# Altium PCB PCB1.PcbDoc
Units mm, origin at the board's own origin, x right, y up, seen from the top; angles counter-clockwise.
Board outline 23.88 x 30.86 mm, 2 copper layers (Top Layer, Bottom Layer); 7 components, 4 nets, 15 pads, 0 vias.
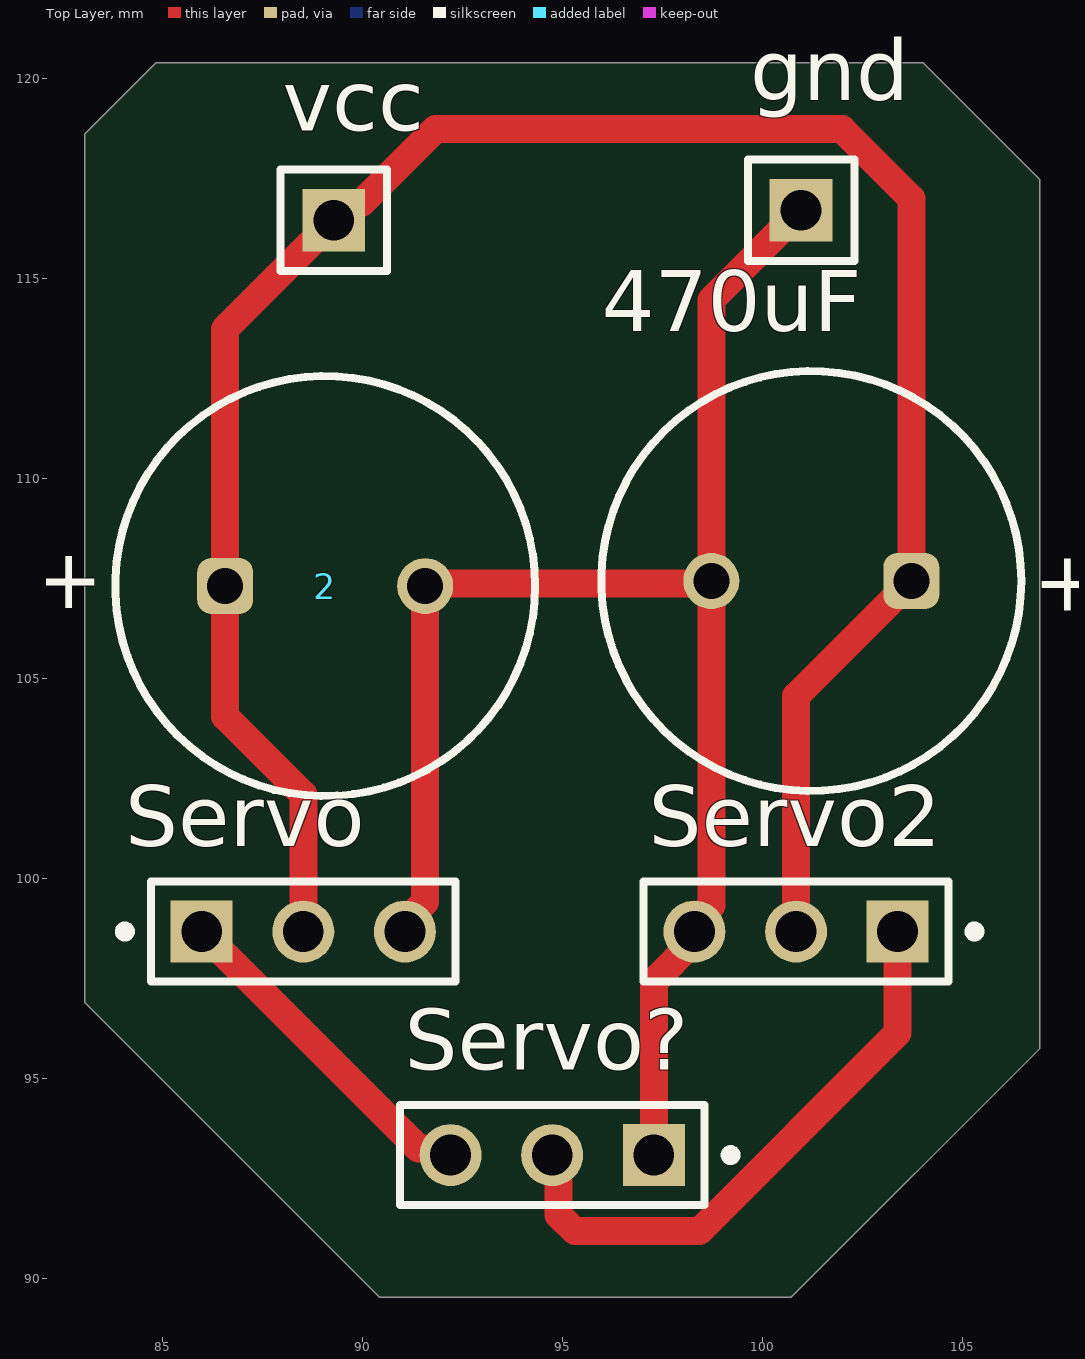
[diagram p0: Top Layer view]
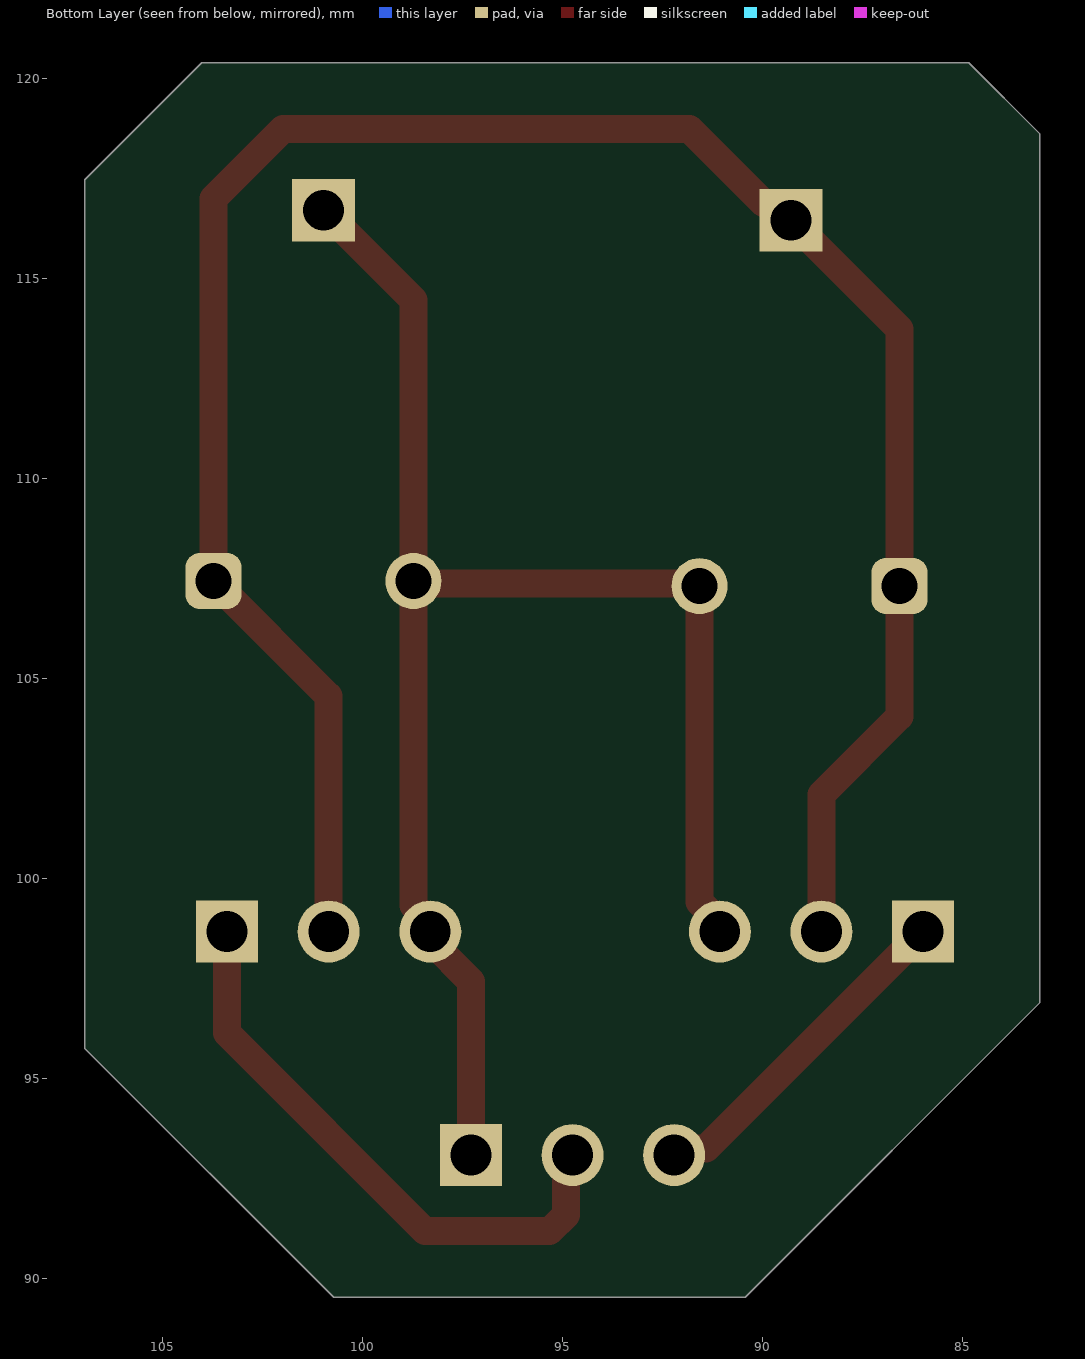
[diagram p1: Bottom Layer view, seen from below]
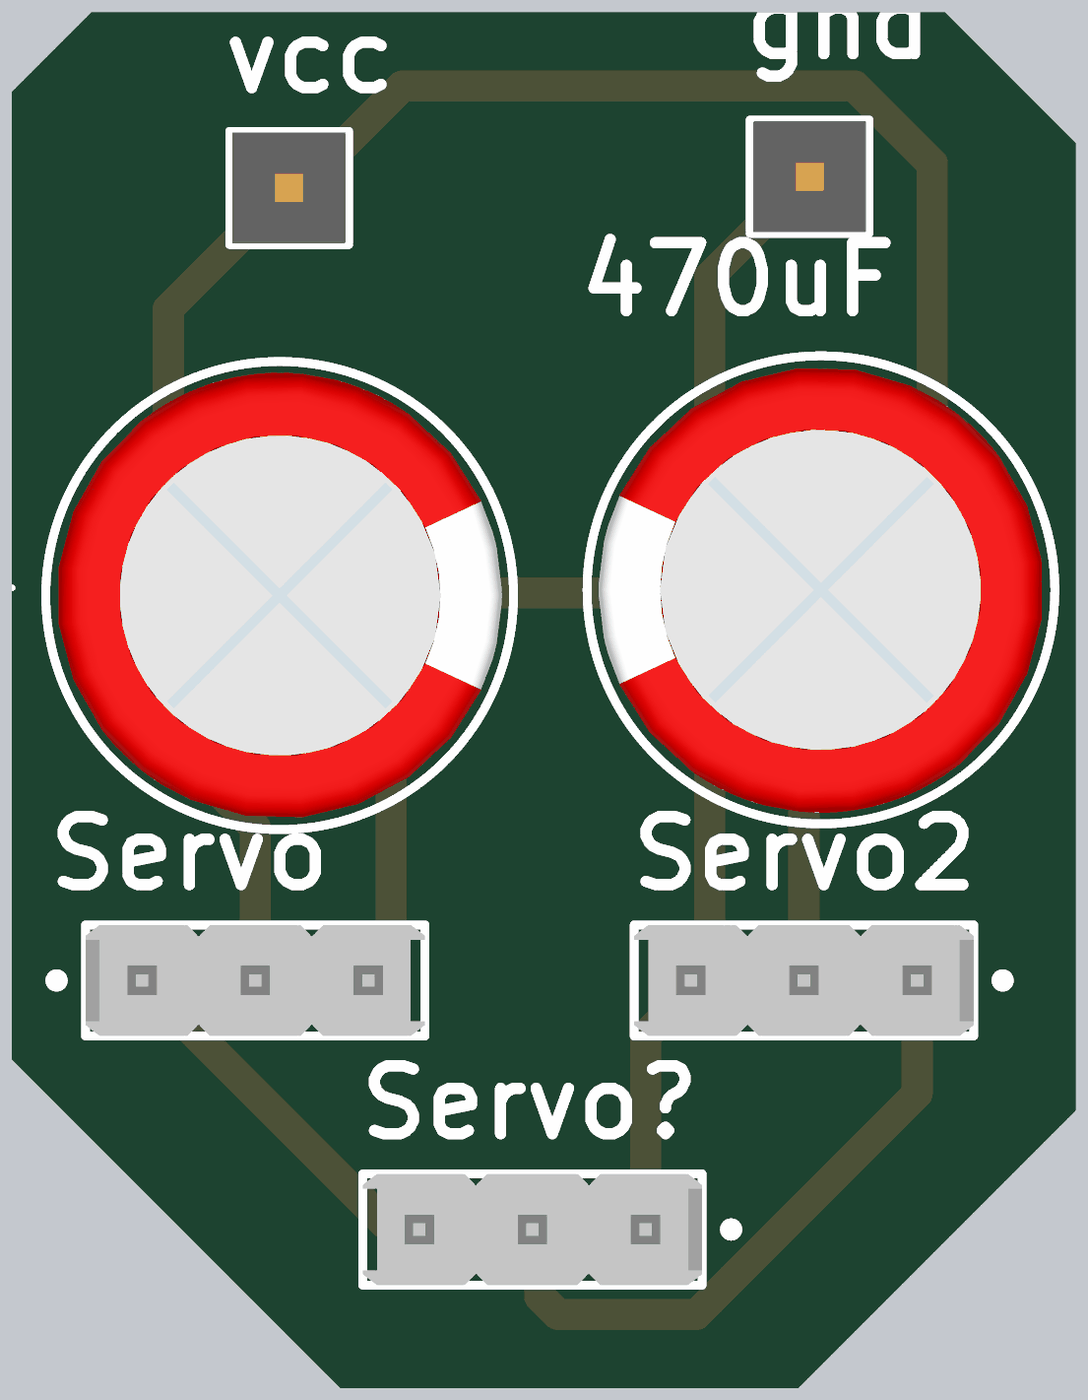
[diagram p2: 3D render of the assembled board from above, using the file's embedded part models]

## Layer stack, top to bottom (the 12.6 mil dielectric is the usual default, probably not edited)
Top Solder: solder mask 0.0102, Solder Resist, Dk 3.5
Top Layer: signal copper 0.0356
Dielectric 1: dielectric 0.32, FR-4, Dk 4.8
Bottom Layer: signal copper 0.0356
Bottom Solder: solder mask 0.0102, Solder Resist, Dk 3.5

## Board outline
83.058,96.901 83.058,118.618 84.836,120.396 104.013,120.396 106.934,117.475 106.934,95.758 100.711,89.535 90.424,89.535

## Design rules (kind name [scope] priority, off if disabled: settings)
Clearance [All] p1: gap=0.254 ignorepadtopadclearanceinfootprint=FALSE
PolygonConnect [All] p1: connectstyle=Relief reliefconductorwidth=0.254 reliefentries=4 polygonreliefangle="90 Angle" airgapwidth=0.254
RoutingVias [All] p1: holewidth=0.711 width=1.27 viastyle="Through Hole" minholewidth=0.711 minwidth=1.27 maxholewidth=0.711 maxwidth=1.27
SolderMaskExpansion [All] p1: expansion=0.102 istentingtop=FALSE
SupplyNets "Schematic Supply Nets_1" [InNet('VCC')] p1: voltage=0.000
SupplyNets "Schematic Supply Nets" [InNet('GND')] p2: voltage=0.000
Width [All] p1: maxlimit=0.7 minlimit=0.7 preferedwidth=0.7 minimp=50.000000 maximp=50.000000 favimp=50.000000
30 further rules are at their usual default settings.

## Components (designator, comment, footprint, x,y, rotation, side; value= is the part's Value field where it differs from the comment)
2 "860040875002" WCAP-ATUL_D10H12.5 89.067,107.315 r180 top
470uF "860040875002" WCAP-ATUL_D10H12.5 101.219,107.442 r0 top
gnd "HTSW-101-07-L-S" FP-HTSW-101-07-L-S-MFG 100.965,116.713 r0 top
Servo "22-28-4033" MOLX-22-28-4033_V 88.519,98.679 r0 top
Servo2 "22-28-4033" MOLX-22-28-4033_V 100.838,98.679 r180 top
Servo? "22-28-4033" MOLX-22-28-4033_V 94.742,93.091 r180 top
vcc "HTSW-101-07-L-S" FP-HTSW-101-07-L-S-MFG 89.281,116.459 r0 top

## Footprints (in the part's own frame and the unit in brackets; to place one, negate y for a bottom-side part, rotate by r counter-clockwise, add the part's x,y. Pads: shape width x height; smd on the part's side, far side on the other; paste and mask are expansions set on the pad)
FP-HTSW-101-07-L-S-MFG [mm]
  rect 1.57x1.57 hole 1.02 paste-2539.97 mask+0: 1(0,0)
  silkscreen extent -1.33,-1.27 1.33,1.27, body extent -1.43,-1.37 1.43,1.37, height 0.25
MOLX-22-28-4033_V [mm] "THD, 3-Leads, Body 7.62x2.49mm, Pitch 2.54mm"
  rect 1.55x1.55 hole 1.02: 1(-2.54,0)
  round 1.55 hole 1.02: 2(0,0) 3(2.54,0)
  silkscreen extent -4.58,-1.24 3.81,1.24, body extent -3.81,-1.24 3.81,1.24, height 8.38
WCAP-ATUL_D10H12.5 [mm] "Aluminum Electrolytic Capacitors, 10x12.5mm"
  rrect50% 1.4x1.4 hole 0.9: 1(2.5,0)
  round 1.4 hole 0.9: 2(-2.5,0)
  silkscreen extent -5.25,-5.25 5.25,5.25, body extent -4.99,-5 5,5, height 12.81

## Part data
2 470uF: library part CMP-03913-53914322-1, "860040875002 WCAP-ATUL Aluminum Electrolytic Capacitors", Capacitance=47µF, Case/Package=Radial, Leakage Current=47µA, Max Operating Temperature=105°C, Min Operating Temperature=-40°C, Ripple Current=400mA, Tolerance=20%, Voltage Rating=100V
gnd vcc: library part CMP-02766-001464-1, "CONN HEADER VERT 1POS", Housing Color=Natural, Max Current Rating=7.6A, Max Operating Temperature=125°C, Max Voltage Rating (AC)=550V, Min Operating Temperature=-55°C
Servo Servo2 Servo?: library part CMP-1676-00001-5, "Male Header, Pitch 2.54 mm, 1 x 3 Position, Height 8.38 mm, Tail Length 3.18 mm, RoHS, Bulk", Colour=Black, Current Rating="4 A", Manufacturer=Molex, Max Operating Temperature="75 degC", Min Operating Temperature="0 degC", Package Quantity=1, Voltage Rating="250 V"

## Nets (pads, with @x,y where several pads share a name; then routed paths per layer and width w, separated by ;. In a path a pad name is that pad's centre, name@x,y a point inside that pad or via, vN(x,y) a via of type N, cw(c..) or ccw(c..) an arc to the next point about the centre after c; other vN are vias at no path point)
GND: 2.2 470uF.2 gnd.1 Servo2.3 Servo.3 Servo?.1 | length 41.2
  Top Layer w0.7: Servo.3 91.059,98.909 91.567,99.417 2.2 91.63,107.379 98.655,107.379 470uF.2 ; Servo?.1 97.282,97.433 98.298,98.449 Servo2.3 98.298,98.909 98.719,99.33 470uF.2 ; gnd.1 98.719,114.467 470uF.2
servo: Servo.1 Servo?.3 | length 8.5
  Top Layer w0.7: Servo.1 91.404,93.254 92.039,93.254 Servo?.3
servo2: Servo2.1 Servo?.2 | length 14.8
  Top Layer w0.7: Servo?.2 94.905,92.928 94.905,91.596 95.315,91.186 98.425,91.186 103.378,96.139 Servo2.1
VCC: 2.1 470uF.1 Servo2.2 Servo.2 vcc.1 | length 55.3
  Top Layer w0.7: Servo.2 88.519,102.108 86.567,104.06 2.1 86.567,113.745 89.716,116.894 89.97,116.894 91.821,118.745 101.981,118.745 103.719,117.007 470uF.1 100.838,104.561 Servo2.2

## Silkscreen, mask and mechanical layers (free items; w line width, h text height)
Mechanical 1:
  the board outline again, w1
